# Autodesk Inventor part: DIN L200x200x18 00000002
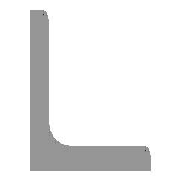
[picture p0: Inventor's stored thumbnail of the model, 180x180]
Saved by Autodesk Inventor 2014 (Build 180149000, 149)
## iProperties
IsCustomPart: 1
Created: 2009-11
Part Number: DIN L200x200x18 00000002
Material: Steel, Mild
Description: Hot-rolled structural steel section-Equal angles
Document SubType Name: Modeling
Standard: DIN
Designer: pokornp
Standard Revision: 1998
Standards Organization: DIN
Language: en-US
Size Designation: L200x200x18
Categories: <MemberInstance><Categories><Category DisplayName="Structural Shapes" InternalName="089c4875-fa83-4c05-b084-43b9cc11f5ed" Mnemonic="GRDR"><CategoryParameter Dis
Stock Number: L200x200x18
Density: 7.86 g/cm^3
Mass: 106464 g
Surface Area: 15515.4 cm^2
Volume: 13545.1 cm^3
Appearance: Steel
_CCFamilyMember: 400
_CCFamilyDisplayName: DIN EN 10056-1 (Hot-rolled structural steel section-Equal angles) - Hot-rolled structural steel section-Equal angles
_FrameMemberDoc: Frame Member File
_Version: 15.0.0
G_L: 1960.000 mm
G_W: 200.000 mm
G_H: 200.000 mm
Author: pokornp
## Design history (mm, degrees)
node "Start plane"
node "End plane"
sketch "Sketch"
  geometry: L1 (-37.533, -19.533)-(-37.533, 135.467); L2 (-55.533, 144.467)-(-46.533, 144.467); L3 (-55.533, -55.533)-(-55.533, 144.467); L4 (-55.533, -55.533)-(144.467, -55.533); L5 (144.467, -46.533)-(144.467, -55.533); L6 (-19.533, -37.533)-(135.467, -37.533); L7 (0, 186.703)-(0, -95.906) reference; L8 (-95.906, 0)-(186.703, 0) reference; A1 r 18 centre (-19.533, -19.533) between (-37.533, -19.533) and (-19.533, -37.533); A2 r 9 centre (-46.533, 135.467) between (-37.533, 135.467) and (-46.533, 144.467); A3 r 9 centre (135.467, -46.533) between (144.467, -46.533) and (135.467, -37.533); 3 further points
  constraints: 12 end point, 6 point on circle, 6 point on line, 6 tangent, 3 centre point, 3 horizontal, 3 vertical, 1 equal radius
  dimensions: "d4" = 200 distance of L3.start L4.end (= b); "d6" = 200 distance of L3.start L2.start (= b); "d8" = 18 distance of point (144.467, -37.533) L4.end (= ParT); "d10" = 18 distance of L2.start point (-37.533, 144.467) (= ParT); "d17" = 18 radius of A1 (= R); "d18" = 9 radius of A2 (= R1); "d19" = 55.53331 distance between parallel lines of L8 L4 (= ex); "d20" = 55.53331 distance between parallel lines of L3 L7 (= d19)
extrude "Body" new body sketch "Sketch" stored distance "d11" = 1960 (= G_L); taper "d12" = 0 deg
node "Driven Length"
  sketch "Sketch3"
    geometry: L1 (0, 0)-(10, 0) reference
    constraints: 2 end point, 1 horizontal
  workplane "Work Plane10"
  sketch "Sketch4"
    geometry: L1 (-2, 0)-(12, 0) reference; L2 (-2, 1960)-(12, 1960) reference
    dimensions: "d24" = 1960 distance between parallel lines of L1 L2 (derived)
body "Solid1"
other parameters: "b" = 200 [user parameter; used in 3 equation terms], "ParT" = 18 [user parameter; used in 3 equation terms], "R" = 18 [user parameter; used in 1 equation term], "R1" = 9 [user parameter; used in 1 equation term], "G_L" = 1960 (= d24) [user parameter; used in 1 equation term], "d7" = 4 (derived), "d9" = 4 (derived), "ex" = 55.53331 (computed from b, ParT) [user parameter; used in 1 equation term], "G_OFFSET_START" = 0 [user parameter; used in 1 equation term], "G_OFFSET_END" = 0 [user parameter; used in 1 equation term], "d21" = 0 (computed from G_OFFSET_START), "d23" = 90 deg
